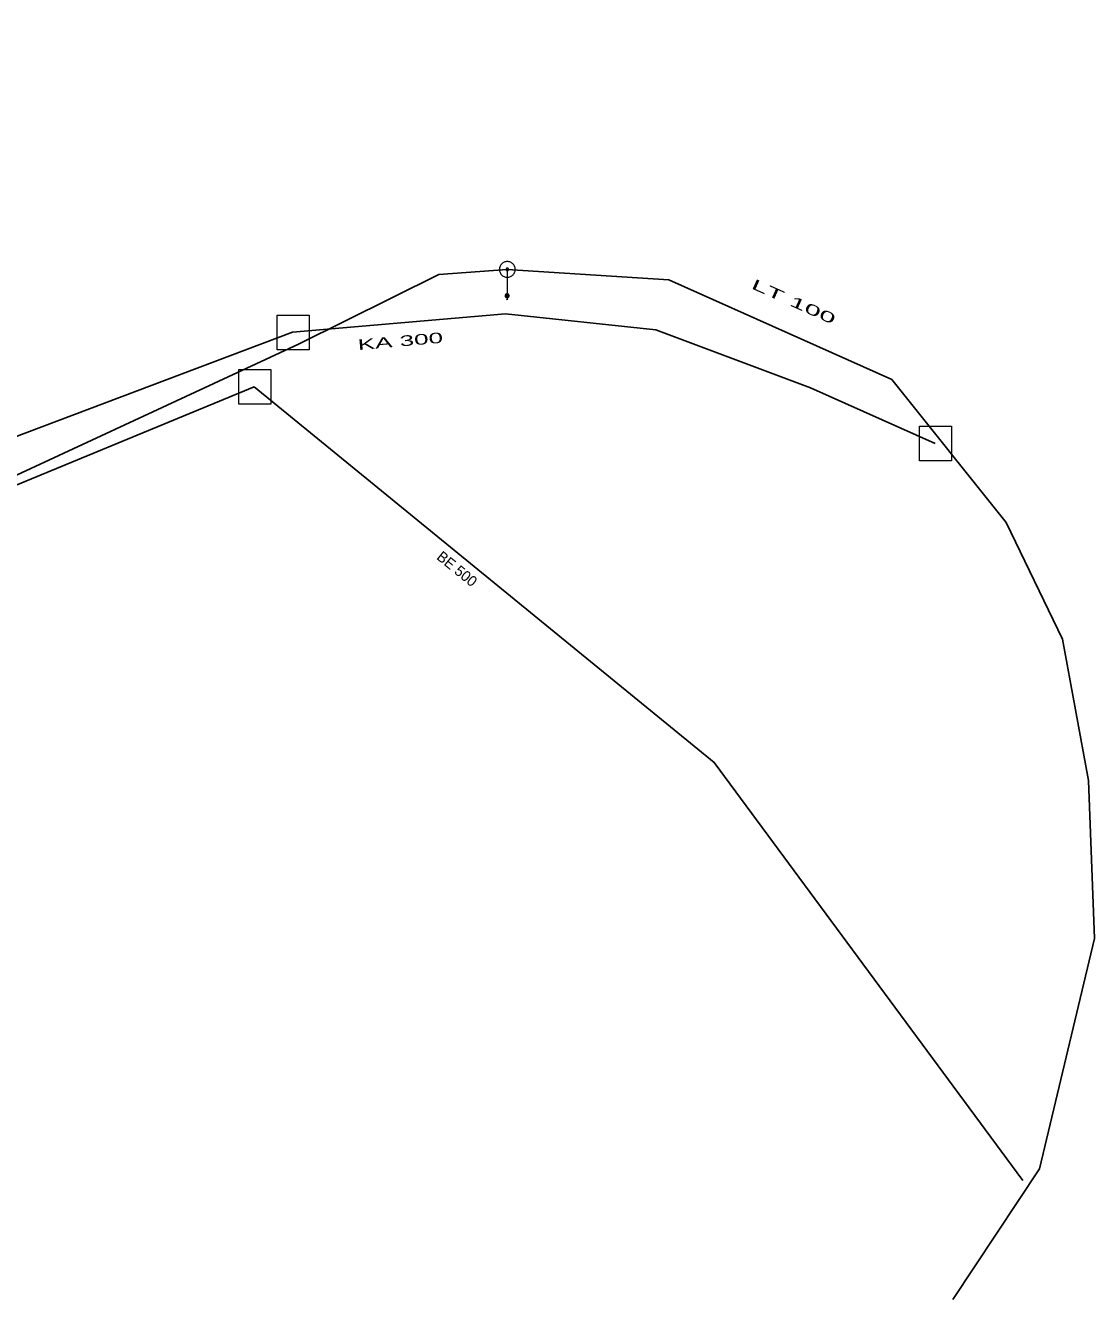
# Model space of a CAD drawing. Extents: x -688432 to -687974, y -973332 to -972704.
# Drawn here: x -688081.3 to -688013.7, y -973082.1 to -973001.6 of the extents above; entities that cross this region are included whole.
import ezdxf
from ezdxf.enums import TextEntityAlignment as Align

# ---------------------------------------------------------------- set-up
doc = ezdxf.new("R2010")
doc.units = 0
doc.header["$LTSCALE"] = 0.27
for name, color, linetype, lineweight in [('1', 7, 'Continuous', 25), ('14', 7, 'Continuous', 25), ('17', 7, 'Continuous', 25), ('22', 7, 'Continuous', 13), ('47', 7, 'Continuous', 13), ('9', 7, 'Continuous', 13)]:
    doc.layers.add(name, color=color, linetype=linetype, lineweight=lineweight)

msp = doc.modelspace()

# ---------------------------------------------------------------- linework, layer by layer
at = {"layer": '14', "lineweight": 13}
msp.add_line((-688050.85, -973016.992), (-688050.858, -973018.659), dxfattribs=at)
at = {"layer": '14'}
for points in [[(-688066.854, -973024.418), (-688085.44, -973032.099), (-688107.27, -973040.32), (-688137.15, -973007.88)], [(-688023.803, -973027.996), (-688031.672, -973024.486), (-688041.452, -973020.817), (-688050.961, -973019.798), (-688064.426, -973020.97)], [(-688064.425, -973020.969), (-688114.84, -973040.004), (-688132.125, -973025.78)], [(-688018.24, -973074.61), (-688037.766, -973048.174), (-688066.854, -973024.418)]]:
    msp.add_lwpolyline(points, dxfattribs=at)
at = {"layer": '17'}
for points in [[(-688050.85, -973016.992), (-688055.169, -973017.307), (-688064.057, -973021.728), (-688087.539, -973032.609), (-688093.627, -973034.653), (-688116.302, -973034.144), (-688128.092, -973024.28), (-688134.442, -973013.736), (-688141.05, -972971.647), (-688145.326, -972926.979)], [(-688022.672, -973082.136), (-688017.199, -973073.873), (-688013.717, -973059.304), (-688014.099, -973049.307), (-688015.75, -973040.379), (-688019.304, -973033), (-688026.539, -973023.956), (-688040.631, -973017.647), (-688050.85, -973016.992)]]:
    msp.add_lwpolyline(points, dxfattribs=at)
at = {"layer": '22'}
for points in [[(-688065.406, -973019.88), (-688063.373, -973019.88), (-688063.373, -973022.073), (-688065.406, -973022.073)], [(-688067.834, -973023.328), (-688065.801, -973023.328), (-688065.801, -973025.521), (-688067.834, -973025.521)], [(-688024.782, -973026.906), (-688022.75, -973026.906), (-688022.75, -973029.099), (-688024.782, -973029.099)]]:
    msp.add_lwpolyline(points, close=True, dxfattribs=at)
at = {"layer": '47'}
for points in [[(-688050.847, -973016.492), (-688050.899, -973016.494), (-688050.951, -973016.502), (-688051.001, -973016.516), (-688051.05, -973016.533), (-688051.097, -973016.557), (-688051.141, -973016.586), (-688051.181, -973016.619), (-688051.219, -973016.656), (-688051.252, -973016.695), (-688051.281, -973016.739), (-688051.305, -973016.786), (-688051.324, -973016.835), (-688051.338, -973016.885), (-688051.346, -973016.937), (-688051.349, -973016.989), (-688051.347, -973017.041), (-688051.339, -973017.093), (-688051.325, -973017.144), (-688051.308, -973017.192), (-688051.284, -973017.239), (-688051.255, -973017.283), (-688051.222, -973017.324), (-688051.186, -973017.362), (-688051.146, -973017.395), (-688051.102, -973017.423), (-688051.055, -973017.447), (-688051.006, -973017.467), (-688050.956, -973017.48), (-688050.904, -973017.488), (-688050.852, -973017.491), (-688050.8, -973017.489), (-688050.748, -973017.481), (-688050.697, -973017.468), (-688050.649, -973017.45), (-688050.602, -973017.426), (-688050.558, -973017.398), (-688050.517, -973017.365), (-688050.479, -973017.329), (-688050.446, -973017.288), (-688050.418, -973017.244), (-688050.394, -973017.197), (-688050.374, -973017.149), (-688050.361, -973017.098), (-688050.353, -973017.046), (-688050.35, -973016.994), (-688050.352, -973016.942), (-688050.36, -973016.89), (-688050.373, -973016.84), (-688050.391, -973016.791), (-688050.415, -973016.744), (-688050.443, -973016.7), (-688050.476, -973016.66), (-688050.513, -973016.622), (-688050.553, -973016.589), (-688050.597, -973016.56), (-688050.644, -973016.536), (-688050.692, -973016.517), (-688050.743, -973016.503), (-688050.795, -973016.495)], [(-688050.849, -973016.91), (-688050.858, -973016.909), (-688050.866, -973016.911), (-688050.874, -973016.913), (-688050.882, -973016.916), (-688050.89, -973016.92), (-688050.897, -973016.925), (-688050.904, -973016.93), (-688050.91, -973016.936), (-688050.915, -973016.943), (-688050.92, -973016.95), (-688050.924, -973016.958), (-688050.927, -973016.966), (-688050.929, -973016.974), (-688050.931, -973016.982), (-688050.931, -973016.991), (-688050.932, -973017), (-688050.93, -973017.008), (-688050.928, -973017.016), (-688050.925, -973017.024), (-688050.921, -973017.032), (-688050.916, -973017.039), (-688050.911, -973017.046), (-688050.905, -973017.052), (-688050.898, -973017.058), (-688050.891, -973017.062), (-688050.883, -973017.066), (-688050.875, -973017.069), (-688050.867, -973017.071), (-688050.859, -973017.073), (-688050.85, -973017.073), (-688050.841, -973017.074), (-688050.833, -973017.072), (-688050.825, -973017.07), (-688050.817, -973017.067), (-688050.809, -973017.063), (-688050.802, -973017.059), (-688050.795, -973017.053), (-688050.789, -973017.047), (-688050.783, -973017.04), (-688050.779, -973017.033), (-688050.775, -973017.025), (-688050.772, -973017.017), (-688050.77, -973017.009), (-688050.768, -973017.001), (-688050.768, -973016.992), (-688050.767, -973016.983), (-688050.769, -973016.975), (-688050.771, -973016.967), (-688050.774, -973016.959), (-688050.778, -973016.951), (-688050.782, -973016.944), (-688050.788, -973016.937), (-688050.794, -973016.931), (-688050.801, -973016.926), (-688050.808, -973016.921), (-688050.816, -973016.917), (-688050.824, -973016.914), (-688050.832, -973016.912), (-688050.84, -973016.91)]]:
    msp.add_lwpolyline(points, close=True, dxfattribs=at)
at = {"layer": '9'}
msp.add_line((-688050.859, -973018.786), (-688050.859, -973018.911), dxfattribs=at)
for points in [[(-688050.985, -973018.658), (-688050.984, -973018.671), (-688050.982, -973018.684), (-688050.979, -973018.697), (-688050.974, -973018.709), (-688050.968, -973018.721), (-688050.961, -973018.732), (-688050.953, -973018.742), (-688050.943, -973018.752), (-688050.933, -973018.76), (-688050.922, -973018.767), (-688050.91, -973018.773), (-688050.898, -973018.778), (-688050.885, -973018.781), (-688050.872, -973018.783), (-688050.859, -973018.786), (-688050.846, -973018.785), (-688050.833, -973018.783), (-688050.82, -973018.78), (-688050.808, -973018.775), (-688050.796, -973018.769), (-688050.785, -973018.762), (-688050.775, -973018.754), (-688050.765, -973018.744), (-688050.757, -973018.734), (-688050.75, -973018.723), (-688050.744, -973018.711), (-688050.739, -973018.699), (-688050.736, -973018.686), (-688050.734, -973018.673), (-688050.732, -973018.66), (-688050.733, -973018.647), (-688050.735, -973018.634), (-688050.738, -973018.621), (-688050.743, -973018.609), (-688050.749, -973018.597), (-688050.756, -973018.586), (-688050.764, -973018.576), (-688050.774, -973018.566), (-688050.784, -973018.558), (-688050.795, -973018.551), (-688050.807, -973018.545), (-688050.819, -973018.54), (-688050.832, -973018.537), (-688050.845, -973018.535), (-688050.858, -973018.532), (-688050.871, -973018.533), (-688050.884, -973018.535), (-688050.897, -973018.538), (-688050.909, -973018.543), (-688050.921, -973018.549), (-688050.932, -973018.556), (-688050.942, -973018.564), (-688050.952, -973018.574), (-688050.96, -973018.584), (-688050.967, -973018.595), (-688050.973, -973018.607), (-688050.978, -973018.619), (-688050.981, -973018.632), (-688050.983, -973018.645)], [(-688050.965, -973018.658), (-688050.965, -973018.669), (-688050.963, -973018.68), (-688050.96, -973018.691), (-688050.956, -973018.701), (-688050.951, -973018.711), (-688050.945, -973018.72), (-688050.938, -973018.729), (-688050.93, -973018.737), (-688050.921, -973018.744), (-688050.912, -973018.75), (-688050.902, -973018.755), (-688050.892, -973018.759), (-688050.881, -973018.762), (-688050.87, -973018.764), (-688050.859, -973018.764), (-688050.848, -973018.766), (-688050.837, -973018.764), (-688050.826, -973018.761), (-688050.816, -973018.757), (-688050.806, -973018.752), (-688050.797, -973018.746), (-688050.788, -973018.739), (-688050.78, -973018.731), (-688050.773, -973018.722), (-688050.767, -973018.713), (-688050.762, -973018.703), (-688050.758, -973018.693), (-688050.755, -973018.682), (-688050.753, -973018.671), (-688050.752, -973018.66), (-688050.752, -973018.649), (-688050.754, -973018.638), (-688050.757, -973018.627), (-688050.761, -973018.617), (-688050.766, -973018.607), (-688050.772, -973018.598), (-688050.779, -973018.589), (-688050.787, -973018.581), (-688050.796, -973018.574), (-688050.805, -973018.568), (-688050.815, -973018.563), (-688050.825, -973018.559), (-688050.836, -973018.556), (-688050.847, -973018.554), (-688050.858, -973018.553), (-688050.869, -973018.552), (-688050.88, -973018.554), (-688050.891, -973018.557), (-688050.901, -973018.561), (-688050.911, -973018.566), (-688050.92, -973018.572), (-688050.929, -973018.579), (-688050.937, -973018.587), (-688050.944, -973018.596), (-688050.95, -973018.605), (-688050.955, -973018.615), (-688050.959, -973018.625), (-688050.962, -973018.636), (-688050.964, -973018.647)], [(-688050.946, -973018.658), (-688050.945, -973018.667), (-688050.944, -973018.676), (-688050.941, -973018.685), (-688050.938, -973018.693), (-688050.934, -973018.701), (-688050.929, -973018.709), (-688050.923, -973018.716), (-688050.917, -973018.722), (-688050.91, -973018.728), (-688050.902, -973018.733), (-688050.894, -973018.737), (-688050.886, -973018.74), (-688050.877, -973018.743), (-688050.868, -973018.744), (-688050.859, -973018.747), (-688050.85, -973018.746), (-688050.841, -973018.745), (-688050.832, -973018.742), (-688050.824, -973018.739), (-688050.816, -973018.735), (-688050.808, -973018.73), (-688050.801, -973018.724), (-688050.795, -973018.718), (-688050.789, -973018.711), (-688050.784, -973018.703), (-688050.78, -973018.695), (-688050.777, -973018.687), (-688050.774, -973018.678), (-688050.773, -973018.669), (-688050.771, -973018.66), (-688050.772, -973018.651), (-688050.773, -973018.642), (-688050.776, -973018.633), (-688050.779, -973018.625), (-688050.783, -973018.617), (-688050.788, -973018.609), (-688050.794, -973018.602), (-688050.8, -973018.596), (-688050.807, -973018.59), (-688050.815, -973018.585), (-688050.823, -973018.581), (-688050.831, -973018.578), (-688050.84, -973018.575), (-688050.849, -973018.574), (-688050.858, -973018.571), (-688050.867, -973018.572), (-688050.876, -973018.573), (-688050.885, -973018.576), (-688050.893, -973018.579), (-688050.901, -973018.583), (-688050.909, -973018.588), (-688050.916, -973018.594), (-688050.922, -973018.6), (-688050.928, -973018.607), (-688050.933, -973018.615), (-688050.937, -973018.623), (-688050.94, -973018.631), (-688050.943, -973018.64), (-688050.944, -973018.649)], [(-688050.926, -973018.658), (-688050.926, -973018.665), (-688050.924, -973018.672), (-688050.923, -973018.679), (-688050.92, -973018.685), (-688050.917, -973018.691), (-688050.913, -973018.697), (-688050.909, -973018.703), (-688050.904, -973018.708), (-688050.898, -973018.712), (-688050.892, -973018.716), (-688050.886, -973018.719), (-688050.88, -973018.722), (-688050.873, -973018.723), (-688050.866, -973018.725), (-688050.859, -973018.725), (-688050.852, -973018.727), (-688050.845, -973018.725), (-688050.838, -973018.724), (-688050.832, -973018.721), (-688050.825, -973018.718), (-688050.82, -973018.714), (-688050.814, -973018.71), (-688050.809, -973018.705), (-688050.805, -973018.699), (-688050.801, -973018.693), (-688050.798, -973018.687), (-688050.795, -973018.681), (-688050.793, -973018.674), (-688050.792, -973018.667), (-688050.791, -973018.66), (-688050.791, -973018.653), (-688050.792, -973018.646), (-688050.794, -973018.639), (-688050.797, -973018.633), (-688050.8, -973018.626), (-688050.804, -973018.621), (-688050.808, -973018.615), (-688050.813, -973018.61), (-688050.819, -973018.606), (-688050.824, -973018.602), (-688050.831, -973018.599), (-688050.837, -973018.596), (-688050.844, -973018.594), (-688050.851, -973018.593), (-688050.858, -973018.592), (-688050.865, -973018.591), (-688050.872, -973018.592), (-688050.879, -973018.594), (-688050.885, -973018.597), (-688050.891, -973018.6), (-688050.897, -973018.604), (-688050.903, -973018.608), (-688050.908, -973018.613), (-688050.912, -973018.619), (-688050.916, -973018.624), (-688050.919, -973018.631), (-688050.922, -973018.637), (-688050.923, -973018.644), (-688050.925, -973018.651)], [(-688050.906, -973018.658), (-688050.906, -973018.663), (-688050.905, -973018.668), (-688050.904, -973018.673), (-688050.902, -973018.677), (-688050.9, -973018.682), (-688050.897, -973018.686), (-688050.894, -973018.689), (-688050.89, -973018.693), (-688050.887, -973018.696), (-688050.883, -973018.699), (-688050.878, -973018.701), (-688050.874, -973018.703), (-688050.869, -973018.704), (-688050.864, -973018.705), (-688050.859, -973018.705), (-688050.854, -973018.707), (-688050.849, -973018.706), (-688050.844, -973018.705), (-688050.84, -973018.703), (-688050.835, -973018.701), (-688050.831, -973018.698), (-688050.827, -973018.695), (-688050.824, -973018.691), (-688050.821, -973018.688), (-688050.818, -973018.684), (-688050.816, -973018.679), (-688050.814, -973018.675), (-688050.813, -973018.67), (-688050.812, -973018.665), (-688050.812, -973018.66), (-688050.811, -973018.655), (-688050.812, -973018.65), (-688050.813, -973018.645), (-688050.815, -973018.641), (-688050.817, -973018.636), (-688050.82, -973018.632), (-688050.823, -973018.628), (-688050.826, -973018.625), (-688050.83, -973018.622), (-688050.834, -973018.619), (-688050.839, -973018.617), (-688050.843, -973018.615), (-688050.848, -973018.614), (-688050.853, -973018.613), (-688050.858, -973018.612), (-688050.863, -973018.611), (-688050.868, -973018.612), (-688050.873, -973018.613), (-688050.877, -973018.615), (-688050.882, -973018.617), (-688050.886, -973018.62), (-688050.889, -973018.623), (-688050.893, -973018.626), (-688050.896, -973018.63), (-688050.899, -973018.634), (-688050.901, -973018.639), (-688050.903, -973018.643), (-688050.904, -973018.648), (-688050.905, -973018.653)], [(-688050.886, -973018.658), (-688050.886, -973018.661), (-688050.886, -973018.664), (-688050.885, -973018.666), (-688050.884, -973018.669), (-688050.883, -973018.672), (-688050.881, -973018.674), (-688050.879, -973018.676), (-688050.877, -973018.678), (-688050.875, -973018.68), (-688050.873, -973018.682), (-688050.87, -973018.683), (-688050.867, -973018.684), (-688050.865, -973018.685), (-688050.862, -973018.685), (-688050.859, -973018.685), (-688050.856, -973018.687), (-688050.853, -973018.687), (-688050.85, -973018.686), (-688050.848, -973018.685), (-688050.845, -973018.684), (-688050.843, -973018.682), (-688050.84, -973018.68), (-688050.838, -973018.678), (-688050.837, -973018.676), (-688050.835, -973018.674), (-688050.834, -973018.671), (-688050.833, -973018.668), (-688050.832, -973018.666), (-688050.832, -973018.663), (-688050.83, -973018.66), (-688050.831, -973018.657), (-688050.831, -973018.654), (-688050.832, -973018.651), (-688050.833, -973018.649), (-688050.834, -973018.646), (-688050.836, -973018.644), (-688050.837, -973018.641), (-688050.839, -973018.639), (-688050.842, -973018.638), (-688050.844, -973018.636), (-688050.847, -973018.635), (-688050.849, -973018.634), (-688050.852, -973018.633), (-688050.855, -973018.633), (-688050.858, -973018.63), (-688050.861, -973018.631), (-688050.864, -973018.631), (-688050.866, -973018.632), (-688050.869, -973018.633), (-688050.872, -973018.634), (-688050.874, -973018.636), (-688050.876, -973018.637), (-688050.878, -973018.639), (-688050.88, -973018.642), (-688050.882, -973018.644), (-688050.883, -973018.647), (-688050.884, -973018.649), (-688050.885, -973018.652), (-688050.885, -973018.655)], [(-688050.867, -973018.658), (-688050.867, -973018.659), (-688050.867, -973018.66), (-688050.866, -973018.66), (-688050.866, -973018.661), (-688050.866, -973018.662), (-688050.865, -973018.663), (-688050.865, -973018.663), (-688050.864, -973018.664), (-688050.864, -973018.664), (-688050.863, -973018.665), (-688050.862, -973018.665), (-688050.861, -973018.665), (-688050.861, -973018.666), (-688050.86, -973018.666), (-688050.859, -973018.666), (-688050.858, -973018.667), (-688050.857, -973018.667), (-688050.857, -973018.667), (-688050.856, -973018.667), (-688050.855, -973018.667), (-688050.854, -973018.666), (-688050.854, -973018.666), (-688050.853, -973018.665), (-688050.853, -973018.665), (-688050.852, -973018.664), (-688050.852, -973018.663), (-688050.851, -973018.662), (-688050.851, -973018.662), (-688050.851, -973018.661), (-688050.85, -973018.66), (-688050.85, -973018.659), (-688050.85, -973018.658), (-688050.85, -973018.658), (-688050.851, -973018.657), (-688050.851, -973018.656), (-688050.852, -973018.655), (-688050.852, -973018.655), (-688050.853, -973018.654), (-688050.853, -973018.654), (-688050.854, -973018.653), (-688050.855, -973018.653), (-688050.856, -973018.652), (-688050.856, -973018.652), (-688050.857, -973018.652), (-688050.858, -973018.651), (-688050.859, -973018.651), (-688050.86, -973018.65), (-688050.86, -973018.65), (-688050.861, -973018.651), (-688050.862, -973018.651), (-688050.863, -973018.652), (-688050.863, -973018.652), (-688050.864, -973018.653), (-688050.864, -973018.653), (-688050.865, -973018.654), (-688050.865, -973018.655), (-688050.865, -973018.656), (-688050.866, -973018.656), (-688050.866, -973018.657)]]:
    msp.add_lwpolyline(points, close=True, dxfattribs=at)
msp.add_lwpolyline([(-688050.828, -973018.877), (-688050.859, -973018.911), (-688050.89, -973018.875)], dxfattribs=at)

# ---------------------------------------------------------------- texts
at = {"layer": '1'}
for s, rotation, width, p in [('LT 100', 336, 2.05, (-688032.8746, -973019.3285)), ('LT 100', 336, 2.05, (-688032.8746, -973019.3285)), ('LT 100', 336, 2.05, (-688032.8746, -973019.3285)), ('LT 100', 336, 2.05, (-688032.8746, -973019.3285)), ('LT 100', 336, 2.05, (-688032.8746, -973019.3285)), ('KA 300', 5, 1.85, (-688057.5821, -973021.8606)), ('KA 300', 5, 1.85, (-688057.5821, -973021.8606)), ('KA 300', 5, 1.85, (-688057.5821, -973021.8606)), ('KA 300', 5, 1.85, (-688057.5821, -973021.8606)), ('KA 300', 5, 1.85, (-688057.5821, -973021.8606))]:
    msp.add_text(s, height=0.6667, rotation=rotation, dxfattribs=dict(at, width=width)).set_placement(p, align=Align.CENTER)
msp.add_text('BE 500', height=0.6667, rotation=321, dxfattribs=at).set_placement((-688054.2342, -973036.1893), align=Align.CENTER)
msp.add_text('BE 500', height=0.6667, rotation=321, dxfattribs=at).set_placement((-688054.2342, -973036.1893), align=Align.CENTER)
msp.add_text('BE 500', height=0.6667, rotation=321, dxfattribs=at).set_placement((-688054.2342, -973036.1893), align=Align.CENTER)
msp.add_text('BE 500', height=0.6667, rotation=321, dxfattribs=at).set_placement((-688054.2342, -973036.1893), align=Align.CENTER)
msp.add_text('BE 500', height=0.6667, rotation=321, dxfattribs=at).set_placement((-688054.2342, -973036.1893), align=Align.CENTER)

doc.saveas('drawing.dxf')
